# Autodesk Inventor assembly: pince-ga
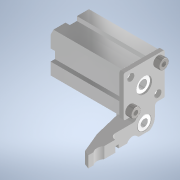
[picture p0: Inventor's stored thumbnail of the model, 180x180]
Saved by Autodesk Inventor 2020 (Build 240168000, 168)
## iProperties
Created: 2023-10
Part Number: pince-ga
Document SubType Name: Assembly
Designer: bruno
Author: bruno
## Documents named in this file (5)
- C:\Users\bruno\Documents\1-Cours-2023-24\Maquettes-Inventor\Pince-robot-Dobot\HS422\pince-ga.iam
- C:\Users\bruno\Documents\1-Cours-2023-24\Maquettes-Inventor\Pince-robot-Dobot\pince-g.ipt
- C:\Users\bruno\Documents\1-Cours-2023-24\Maquettes-Inventor\Pince-robot-Dobot\Douille.ipt
- C:\Users\bruno\Documents\1-Cours-2023-24\Maquettes-Inventor\Pince-robot-Dobot\corps-verin.ipt
- C:\Users\bruno\Documents\Inventor\Content Center Files\R2020\fr-FR\KS B 1003\KS B 1003 - M 4 x 8.ipt
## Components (5 placed, 4 different names)
1. pince-g:1 — Placage:1, Affleurement:1, Placage:2, Placage:3, Angle:1, Logement:1, Logement:2
2. Douille:1 — Placage:1, Affleurement:1
3. corps-verin:1 — Placage:2, Placage:3, Angle:1
4. KS B 1003 - Métrique M 4 x 8:1 — Logement:1
5. KS B 1003 - Métrique M 4 x 8:2 — Logement:2
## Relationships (7: Mate 3, Insert 2, Flush 1, Angle 1)
- Placage:1 [Mate]: pince-g:1 ↔ Douille:1
- Affleurement:1 [Flush]: pince-g:1 ↔ Douille:1
- Placage:2 [Mate]: pince-g:1 ↔ corps-verin:1
- Placage:3 [Mate]: pince-g:1 ↔ corps-verin:1
- Angle:1: pince-g:1 ↔ corps-verin:1
- Logement:1 [Insert]: pince-g:1 ↔ KS B 1003 - Métrique M 4 x 8:1
- Logement:2 [Insert]: pince-g:1 ↔ KS B 1003 - Métrique M 4 x 8:2
